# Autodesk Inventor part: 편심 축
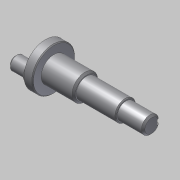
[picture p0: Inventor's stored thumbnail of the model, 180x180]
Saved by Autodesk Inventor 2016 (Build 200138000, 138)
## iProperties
Created: 2015-10
Part Number: 편심 축
Document SubType Name: Modeling
Designer: mdu
Density: 7.86 g/cm^3
Material: 강철, 연강
Mass: 78.4913 g
Surface Area: 37.9919 cm^2
Volume: 9.98617 cm^3
Appearance: 기본값
Author: mdu
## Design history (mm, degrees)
sketch "스케치1"
  geometry: L1 (1.75, -12.001)-(1.75, 11.999) reference; L2 (-16.95, -14)-(-16.95, 14) reference; L3 (-36.25, -18.06)-(-36.25, 18.06) reference; L4 (-41.25, 0)-(20.75, 0); L5 (-41.25, 0)-(-41.25, 12.5); L6 (-41.25, 12.5)-(-36.25, 12.5); L7 (-36.25, 12.5)-(-36.25, 7.5); L8 (-36.25, 7.5)-(-17.25, 7.5); L9 (-17.25, 6)-(5.75, 6); L10 (20.75, 5)-(20.75, 0); L11 (5.75, 6)-(5.75, 5); L12 (5.75, 5)-(20.75, 5); L13 (-17.25, -13.7)-(-17.25, 13.7) reference; L14 (-17.25, 7.5)-(-17.25, 6); 2 further points
  constraints: 20 end point, 7 perpendicular, 5 point on line, 1 collinear, 1 midpoint, 1 parallel
  dimensions: "d0" = 12 diameter of L9 L4; "d1" = 15 diameter of L8 L4; "d2" = 25 diameter of L6 L4; "d3" = 5 distance of L5.end L6.end; "d4" = 62 distance of L4.start L4.end; "d5" = 10 diameter of L12 L4; "d6" = 15 distance of L11.end L10.start
revolve "회전1" sketch "스케치1" stored, may be unused: angle "d7" = 90 deg
sketch "스케치2"
  geometry: C1 r 4 at (0, -7.5); C2 r 5 at (0, -7.5); C3 r 12.5 at (0, 0) reference; 1 further point
  constraints: 2 centre point, 1 coincident, 1 tangent, 1 vertical alignment
  dimensions: "d8" = 8 diameter of C1; "d9" = 7.5 distance of point (0, 0) C1.centre
extrude "돌출1" join sketch "스케치2" distance "d10" = 10; taper "d11" = 0 deg
extrude "돌출2" join sketch "스케치2" distance "d12" = 0.5; taper "d13" = 0 deg
node "작업 평면1"
sketch "스케치3"
  geometry: L1 (-7.5, 5)-(-7.5, -5) reference; L2 (-7.5, 1.5)-(3, 1.5); L3 (3, -1.5)-(-7.5, -1.5); A1 r 1.5 centre (3, 0) between (3, -1.5) and (3, 1.5); 2 further points
  constraints: 4 end point, 2 perpendicular, 2 point on circle, 2 point on line, 2 tangent, 1 centre point, 1 horizontal alignment, 1 midpoint
  dimensions: "d14" = 3 distance between parallel lines of L3 L2; "d15" = 12 dimension on A1 L1
extrude "돌출3" cut sketch "스케치3" distance "d16" = 1.8; taper "d17" = 0 deg
chamfer "모따기1" distance "d18" = 1; stored, may be unused: second distance "d19" = 2, angle "d20" = 45 deg
chamfer "모따기2" distance "d21" = 0.5; stored, may be unused: second distance "d22" = 2, angle "d23" = 45 deg
node "솔리드1"
node "참조1"
node "참조2"
node "참조3"
node "참조4"
